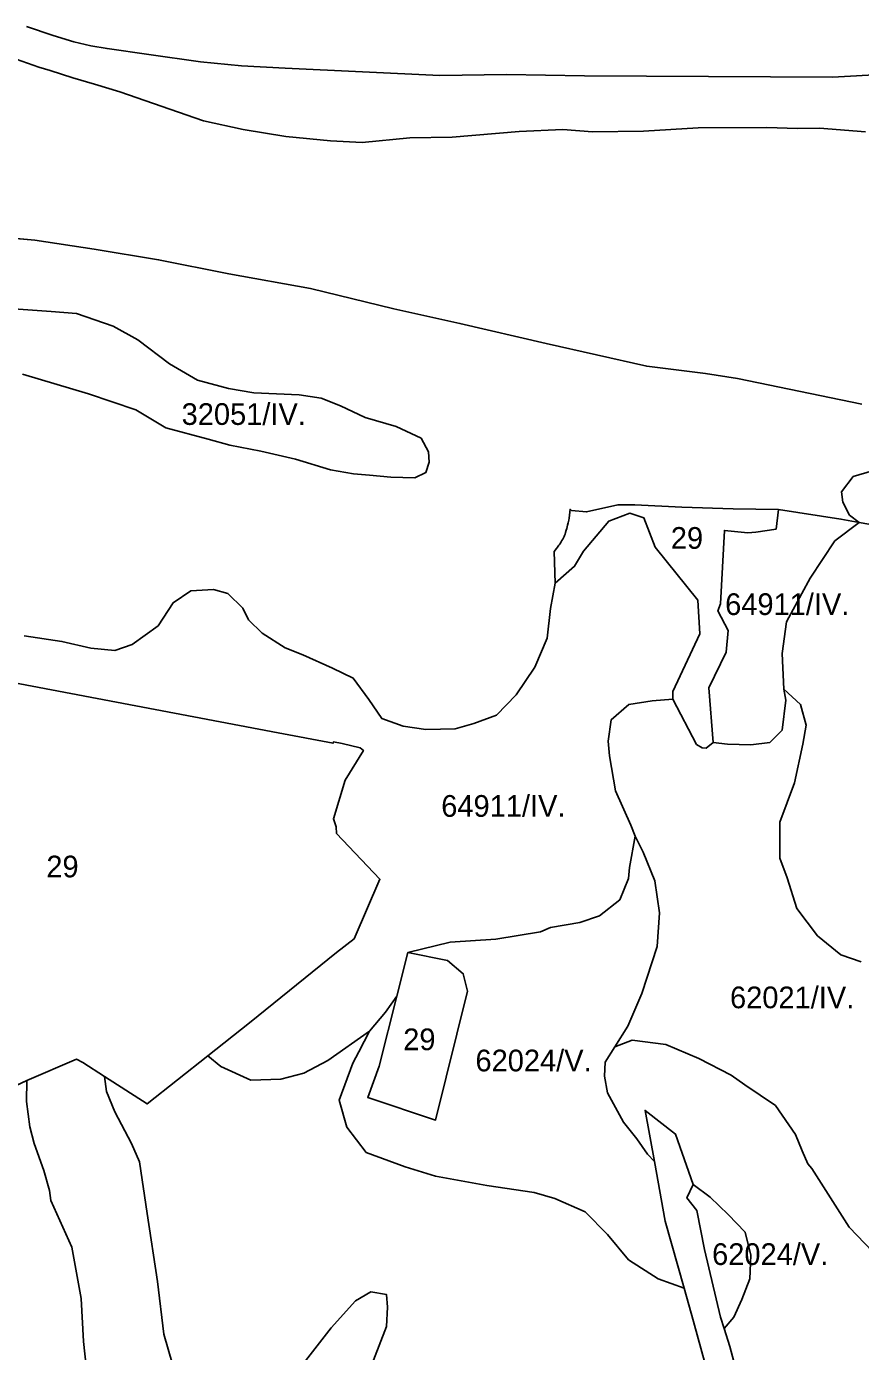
# Model space of a CAD drawing. Extents: x -521621 to -516761, y -1190184 to -1184927.
# Drawn here: x -519686 to -519109, y -1188092 to -1187176 of the extents above; entities that cross this region are included whole.
import ezdxf

# ---------------------------------------------------------------- set-up
doc = ezdxf.new("R2010")
doc.units = 0
doc.layers.add('BPEJ_s', color=7, linetype='Continuous')

msp = doc.modelspace()

# ---------------------------------------------------------------- linework, layer by layer
at = {"layer": 'BPEJ_s'}
for p, q in [((-519667.22, -1187182.03), (-519685.69, -1187175.9)), ((-519652.89, -1187186.47), (-519667.22, -1187182.03)), ((-519641.3, -1187189.2), (-519652.89, -1187186.47)), ((-519629.99, -1187191.18), (-519641.3, -1187189.2)), ((-519601.06, -1187195.24), (-519629.99, -1187191.18)), ((-519565.43, -1187200.37), (-519601.06, -1187195.24)), ((-519536.97, -1187203.2), (-519565.43, -1187200.37)), ((-519506.81, -1187204.71), (-519536.97, -1187203.2)), ((-519400, -1187209.9), (-519506.81, -1187204.71)), ((-519353.85, -1187209.13), (-519400, -1187209.9)), ((-519299.97, -1187210.03), (-519353.85, -1187209.13)), ((-519128.66, -1187211.03), (-519299.97, -1187210.03)), ((-519112.11, -1187210), (-519128.66, -1187211.03)), ((-519092.1, -1187208.96), (-519112.11, -1187210)), ((-519733.29, -1187318.93), (-519679.94, -1187323.59)), ((-519679.94, -1187323.59), (-519638.88, -1187329.95)), ((-519638.88, -1187329.95), (-519594.42, -1187337.15)), ((-519594.42, -1187337.15), (-519545.74, -1187346.89)), ((-519545.74, -1187346.89), (-519489.43, -1187357.06)), ((-519489.43, -1187357.06), (-519431.85, -1187371.04)), ((-519668.66, -1187373.03), (-519694.32, -1187371.13)), ((-519651.08, -1187374.46), (-519668.66, -1187373.03)), ((-519625.89, -1187383.02), (-519651.08, -1187374.46)), ((-519431.85, -1187371.04), (-519386.13, -1187381.21)), ((-519608.78, -1187392.53), (-519625.89, -1187383.02)), ((-519386.13, -1187381.21), (-519326.43, -1187395.19)), ((-519586.93, -1187409.17), (-519608.78, -1187392.53)), ((-519326.43, -1187395.19), (-519257, -1187410.86)), ((-519567.44, -1187420.58), (-519586.93, -1187409.17)), ((-519257, -1187410.86), (-519216.36, -1187415.95)), ((-519688.33, -1187416.31), (-519642.89, -1187429.9)), ((-519546.06, -1187426.29), (-519567.44, -1187420.58)), ((-519216.36, -1187415.95), (-519194.34, -1187419.33)), ((-519194.34, -1187419.33), (-519108.4, -1187437.13)), ((-519642.89, -1187429.9), (-519610.01, -1187441.1)), ((-519528.48, -1187429.14), (-519546.06, -1187426.29)), ((-519497.12, -1187430.57), (-519528.48, -1187429.14)), ((-519481.91, -1187432.94), (-519497.12, -1187430.57)), ((-519468.6, -1187438.17), (-519481.91, -1187432.94)), ((-519610.01, -1187441.1), (-519589.34, -1187453.42)), ((-519451.5, -1187446.26), (-519468.6, -1187438.17)), ((-519430.11, -1187452.44), (-519451.5, -1187446.26)), ((-519589.34, -1187453.42), (-519560.09, -1187461.28)), ((-519560.09, -1187461.28), (-519545.1, -1187465.54)), ((-519413.01, -1187460.52), (-519430.11, -1187452.44)), ((-519407.78, -1187470.03), (-519413.01, -1187460.52)), ((-519545.1, -1187465.54), (-519523.8, -1187469.49)), ((-519523.8, -1187469.49), (-519499.82, -1187475.02)), ((-519407.31, -1187477.16), (-519407.78, -1187470.03)), ((-519499.82, -1187475.02), (-519475.49, -1187482.38)), ((-519409.68, -1187484.3), (-519407.31, -1187477.16)), ((-519475.49, -1187482.38), (-519459.58, -1187485.25)), ((-519459.58, -1187485.25), (-519448.65, -1187486.2)), ((-519448.65, -1187486.2), (-519433.92, -1187487.62)), ((-519433.92, -1187487.62), (-519417.28, -1187488.1)), ((-519417.28, -1187488.1), (-519409.68, -1187484.3)), ((-519114.33, -1187487.11), (-519122.37, -1187497.71)), ((-519091.46, -1187480.34), (-519114.33, -1187487.11)), ((-519122.37, -1187497.71), (-519121.52, -1187504.91)), ((-519277.01, -1187506.71), (-519298.64, -1187511.54)), ((-519265.28, -1187506.76), (-519277.01, -1187506.71)), ((-519232.85, -1187508.38), (-519265.28, -1187506.76)), ((-519121.52, -1187504.91), (-519116.87, -1187513.8)), ((-519310.7, -1187515.97), (-519310.93, -1187517.36)), ((-519310.41, -1187513.76), (-519310.7, -1187515.97)), ((-519310.01, -1187509.72), (-519310.41, -1187513.76)), ((-519308.94, -1187510.56), (-519310.01, -1187509.72)), ((-519298.64, -1187511.54), (-519308.94, -1187510.56)), ((-519197.25, -1187509.54), (-519232.85, -1187508.38)), ((-519165.96, -1187509.87), (-519197.25, -1187509.54)), ((-519122.78, -1187516.59), (-519165.96, -1187509.87)), ((-519116.87, -1187513.8), (-519110.16, -1187518.97)), ((-519312.6, -1187524.31), (-519313.08, -1187525.9)), ((-519312.25, -1187523.11), (-519312.6, -1187524.31)), ((-519311.66, -1187520.8), (-519312.25, -1187523.11)), ((-519311.26, -1187519.05), (-519311.66, -1187520.8)), ((-519310.93, -1187517.36), (-519311.26, -1187519.05)), ((-519110.16, -1187518.97), (-519122.78, -1187516.59)), ((-519317.68, -1187534.57), (-519318.15, -1187535.24)), ((-519317.17, -1187533.79), (-519317.68, -1187534.57)), ((-519316.15, -1187532.17), (-519317.17, -1187533.79)), ((-519315.65, -1187531.35), (-519316.15, -1187532.17)), ((-519315.08, -1187530.38), (-519315.65, -1187531.35)), ((-519314.59, -1187529.47), (-519315.08, -1187530.38)), ((-519314.19, -1187528.68), (-519314.59, -1187529.47)), ((-519313.82, -1187527.87), (-519314.19, -1187528.68)), ((-519313.45, -1187526.94), (-519313.82, -1187527.87)), ((-519313.08, -1187525.9), (-519313.45, -1187526.94)), ((-519319.39, -1187536.9), (-519321.02, -1187538.88)), ((-519321.02, -1187538.88), (-519320.31, -1187560.93)), ((-519318.69, -1187535.99), (-519319.39, -1187536.9)), ((-519318.15, -1187535.24), (-519318.69, -1187535.99)), ((-519320.31, -1187560.93), (-519323.61, -1187578.33)), ((-519572.15, -1187566.12), (-519584.35, -1187574.45)), ((-519556.33, -1187565.29), (-519572.15, -1187566.12)), ((-519546.63, -1187568.06), (-519556.33, -1187565.29)), ((-519536.09, -1187578.06), (-519546.63, -1187568.06)), ((-519584.35, -1187574.45), (-519594.61, -1187590.27)), ((-519532.2, -1187586.11), (-519536.09, -1187578.06)), ((-519323.61, -1187578.33), (-519325.83, -1187598.87)), ((-519522.77, -1187595.54), (-519532.2, -1187586.11)), ((-519661.18, -1187601.09), (-519687.26, -1187597.21)), ((-519594.61, -1187590.27), (-519612.64, -1187603.31)), ((-519506.96, -1187605.53), (-519522.77, -1187595.54)), ((-519641.21, -1187605.81), (-519661.18, -1187601.09)), ((-519624.57, -1187607.48), (-519641.21, -1187605.81)), ((-519612.64, -1187603.31), (-519624.57, -1187607.48)), ((-519494.76, -1187610.53), (-519506.96, -1187605.53)), ((-519325.83, -1187598.87), (-519334.43, -1187618.86)), ((-519474.23, -1187619.69), (-519494.76, -1187610.53)), ((-519459.81, -1187626.63), (-519474.23, -1187619.69)), ((-519334.43, -1187618.86), (-519347.19, -1187638.01)), ((-519448.99, -1187641.34), (-519459.81, -1187626.63)), ((-519440.11, -1187654.38), (-519448.99, -1187641.34)), ((-519347.19, -1187638.01), (-519360.78, -1187652.16)), ((-519360.78, -1187652.16), (-519376.59, -1187657.99)), ((-519425.41, -1187659.66), (-519440.11, -1187654.38)), ((-519409.6, -1187662.15), (-519425.41, -1187659.66)), ((-519389.35, -1187661.6), (-519409.6, -1187662.15)), ((-519376.59, -1187657.99), (-519389.35, -1187661.6)), ((-519710.91, -1187916.7), (-519685.53, -1187904.73)), ((-519685.53, -1187904.73), (-519685.65, -1187919.2)), ((-519685.65, -1187919.2), (-519683.42, -1187936.76)), ((-519683.42, -1187936.76), (-519680.31, -1187948.33)), ((-519680.31, -1187948.33), (-519673.65, -1187967)), ((-519673.65, -1187967), (-519669.87, -1187980.79)), ((-519669.87, -1187980.79), (-519668.9, -1187987.88)), ((-519668.9, -1187987.88), (-519654.42, -1188020.09)), ((-519654.42, -1188020.09), (-519647.98, -1188055.52)), ((-519647.98, -1188055.52), (-519646.37, -1188085.32)), ((-519646.37, -1188085.32), (-519639.13, -1188151.35))]:
    msp.add_line(p, q, dxfattribs=at)
for points in [[(-519685.69, -1187175.9), (-519667.22, -1187182.03), (-519652.89, -1187186.47), (-519641.3, -1187189.2), (-519629.99, -1187191.18), (-519601.06, -1187195.24), (-519565.43, -1187200.37), (-519536.97, -1187203.2), (-519506.81, -1187204.71), (-519400, -1187209.9), (-519353.85, -1187209.13), (-519299.97, -1187210.03), (-519128.66, -1187211.03), (-519112.11, -1187210), (-519092.1, -1187208.96), (-519064.5, -1187207.92), (-519024.83, -1187208.61), (-519003.79, -1187209.3), (-518919.06, -1187210.79), (-518913.41, -1187211.72)], [(-519696.84, -1187197.02), (-519677.05, -1187204.06), (-519669.31, -1187206.37), (-519653.61, -1187211.29), (-519638.75, -1187215.67), (-519621.13, -1187221.16), (-519563.24, -1187241.16), (-519535.84, -1187247.13), (-519506.38, -1187252.08), (-519475.48, -1187254.97), (-519453.65, -1187256.21), (-519420.68, -1187252.91), (-519391.43, -1187252.49), (-519345.28, -1187248.58), (-519315, -1187247.13), (-519294.6, -1187248.78), (-519259.17, -1187248.17), (-519221.47, -1187245.9), (-519174.09, -1187245.69), (-519152.82, -1187246.42), (-519137.62, -1187246.1), (-519105.9, -1187248.79)], [(-519105.9, -1187248.79), (-519137.62, -1187246.1), (-519152.82, -1187246.42), (-519174.09, -1187245.69), (-519221.47, -1187245.9), (-519259.17, -1187248.17), (-519294.6, -1187248.78), (-519315, -1187247.13), (-519345.28, -1187248.58), (-519391.43, -1187252.49), (-519420.68, -1187252.91), (-519453.65, -1187256.21), (-519475.48, -1187254.97), (-519506.38, -1187252.08), (-519535.84, -1187247.13), (-519563.24, -1187241.16), (-519621.13, -1187221.16), (-519638.75, -1187215.67), (-519653.61, -1187211.29), (-519669.31, -1187206.37), (-519677.05, -1187204.06), (-519696.84, -1187197.02)], [(-519108.4, -1187437.13), (-519194.34, -1187419.33), (-519216.36, -1187415.95), (-519257, -1187410.86), (-519326.43, -1187395.19), (-519386.13, -1187381.21), (-519431.85, -1187371.04), (-519489.43, -1187357.06), (-519545.74, -1187346.89), (-519594.42, -1187337.15), (-519638.88, -1187329.95), (-519679.94, -1187323.59), (-519733.29, -1187318.93)], [(-519694.32, -1187371.13), (-519668.66, -1187373.03), (-519651.08, -1187374.46), (-519625.89, -1187383.02), (-519608.78, -1187392.53), (-519586.93, -1187409.17), (-519567.44, -1187420.58), (-519546.06, -1187426.29), (-519528.48, -1187429.14), (-519497.12, -1187430.57), (-519481.91, -1187432.94), (-519468.6, -1187438.17), (-519451.5, -1187446.26), (-519430.11, -1187452.44), (-519413.01, -1187460.52), (-519407.78, -1187470.03), (-519407.31, -1187477.16), (-519409.68, -1187484.3), (-519417.28, -1187488.1), (-519433.92, -1187487.62), (-519448.65, -1187486.2), (-519459.58, -1187485.25), (-519475.49, -1187482.38), (-519499.82, -1187475.02), (-519523.8, -1187469.49), (-519545.1, -1187465.54), (-519560.09, -1187461.28), (-519589.34, -1187453.42), (-519610.01, -1187441.1), (-519642.89, -1187429.9), (-519688.33, -1187416.31)], [(-519055.51, -1187528.45), (-519110.16, -1187518.97), (-519116.87, -1187513.8), (-519121.52, -1187504.91), (-519122.37, -1187497.71), (-519114.33, -1187487.11), (-519091.46, -1187480.34)], [(-519687.26, -1187597.21), (-519661.18, -1187601.09), (-519641.21, -1187605.81), (-519624.57, -1187607.48), (-519612.64, -1187603.31), (-519594.61, -1187590.27), (-519584.35, -1187574.45), (-519572.15, -1187566.12), (-519556.33, -1187565.29), (-519546.63, -1187568.06), (-519536.09, -1187578.06), (-519532.2, -1187586.11), (-519522.77, -1187595.54), (-519506.96, -1187605.53), (-519494.76, -1187610.53), (-519474.23, -1187619.69), (-519459.81, -1187626.63), (-519448.99, -1187641.34), (-519440.11, -1187654.38), (-519425.41, -1187659.66), (-519409.6, -1187662.15), (-519389.35, -1187661.6), (-519376.59, -1187657.99), (-519360.78, -1187652.16), (-519347.19, -1187638.01), (-519334.43, -1187618.86), (-519325.83, -1187598.87), (-519323.61, -1187578.33), (-519320.31, -1187560.93), (-519306.91, -1187549.18), (-519300.78, -1187538.69), (-519283.32, -1187517.95), (-519268.8, -1187512.49), (-519258.98, -1187515.74), (-519251.29, -1187535.93), (-519221.71, -1187572.62), (-519220.42, -1187595.79), (-519239.07, -1187635.7), (-519239.07, -1187641.18), (-519253.19, -1187642.16), (-519269.28, -1187644.7), (-519281.56, -1187655.29), (-519283.67, -1187670.12), (-519282.83, -1187680.29), (-519278.59, -1187704.44), (-519268.01, -1187728.16), (-519265.04, -1187735.78), (-519268.85, -1187757.39), (-519269.7, -1187765.01), (-519275.63, -1187779.84), (-519289.6, -1187790.85), (-519303.15, -1187795.52), (-519323.47, -1187798.9), (-519330.33, -1187802.04), (-519361.24, -1187806.96), (-519392.85, -1187809.07), (-519422.03, -1187816.17), (-519429.72, -1187846.45), (-519437.46, -1187857.57), (-519448.7, -1187870.58), (-519477.51, -1187890.97), (-519494.02, -1187899.75), (-519509.82, -1187903.97), (-519530.55, -1187904.67), (-519551.27, -1187895.18), (-519560.37, -1187887.81), (-519531.55, -1187865), (-519471.37, -1187816.27), (-519459.2, -1187806.79), (-519441.4, -1187765.6), (-519471.42, -1187734.06), (-519471.72, -1187729.26), (-519473.52, -1187723.85), (-519465.47, -1187697.1), (-519452.88, -1187676.55), (-519455.1, -1187674.65), (-519467.57, -1187671.74), (-519473.61, -1187670.59), (-519473.79, -1187671.56), (-519511.79, -1187664.33), (-519695.16, -1187629.58)], [(-519108.82, -1187822.63), (-519122.79, -1187817.97), (-519138.88, -1187804.83), (-519153.28, -1187785.77), (-519160.05, -1187764.59), (-519165.13, -1187751.03), (-519165.13, -1187726.04), (-519154.97, -1187698.93), (-519149.04, -1187672.24), (-519146.93, -1187659.11), (-519150.74, -1187644.7), (-519162.17, -1187634.11), (-519163.44, -1187609.54), (-519160.47, -1187587.51), (-519149.89, -1187568.03), (-519143.96, -1187557.44), (-519127.03, -1187531.59), (-519110.16, -1187518.97), (-519055.51, -1187528.45)], [(-519695.16, -1187629.58), (-519511.79, -1187664.33), (-519473.79, -1187671.56), (-519473.61, -1187670.59), (-519467.57, -1187671.74), (-519455.1, -1187674.65), (-519452.88, -1187676.55), (-519465.47, -1187697.1), (-519473.52, -1187723.85), (-519471.72, -1187729.26), (-519471.42, -1187734.06), (-519441.4, -1187765.6), (-519459.2, -1187806.79), (-519471.37, -1187816.27), (-519531.55, -1187865), (-519560.37, -1187887.81), (-519602.33, -1187921.01), (-519631.66, -1187902.09), (-519646.68, -1187892.41), (-519651.15, -1187890.15), (-519685.53, -1187904.73), (-519710.91, -1187916.7)], [(-519095.38, -1188028.82), (-519117.18, -1188006.2), (-519142.95, -1187965.74), (-519145.66, -1187962.42), (-519149.47, -1187953.53), (-519154.12, -1187942.09), (-519168.09, -1187922.18), (-519189.26, -1187907.78), (-519198.58, -1187901), (-519221.01, -1187889.56), (-519243.88, -1187879.82), (-519267.16, -1187876.85), (-519279.02, -1187881.51), (-519270.12, -1187867.11), (-519260.39, -1187844.66), (-519249.8, -1187812.04), (-519248.11, -1187788.74), (-519251.5, -1187766.71), (-519259.54, -1187746.8), (-519265.04, -1187735.78), (-519268.01, -1187728.16), (-519278.59, -1187704.44), (-519282.83, -1187680.29), (-519283.67, -1187670.12), (-519281.56, -1187655.29), (-519269.28, -1187644.7), (-519253.19, -1187642.16), (-519239.07, -1187641.18), (-519222.67, -1187672.4), (-519218.81, -1187674.65), (-519215.92, -1187674.97), (-519211.1, -1187671.11), (-519201.12, -1187672.24), (-519185.03, -1187672.66), (-519171.9, -1187670.97), (-519163.44, -1187662.5), (-519160.9, -1187641.74), (-519162.17, -1187634.11), (-519150.74, -1187644.7), (-519146.93, -1187659.11), (-519149.04, -1187672.24), (-519154.97, -1187698.93), (-519165.13, -1187726.04), (-519165.13, -1187751.03), (-519160.05, -1187764.59), (-519153.28, -1187785.77), (-519138.88, -1187804.83), (-519122.79, -1187817.97), (-519108.82, -1187822.63)], [(-519581.87, -1188111.43), (-519590.76, -1188080.3), (-519595.2, -1188043.83), (-519602.31, -1187996.69), (-519607.65, -1187961.11), (-519613.1, -1187948.26), (-519624.69, -1187926.47), (-519630.31, -1187912.41), (-519631.66, -1187902.09), (-519602.33, -1187921.01), (-519560.37, -1187887.81), (-519551.27, -1187895.18), (-519530.55, -1187904.67), (-519509.82, -1187903.97), (-519494.02, -1187899.75), (-519477.51, -1187890.97), (-519448.7, -1187870.58), (-519456.08, -1187884.99), (-519460.21, -1187892.8), (-519469.54, -1187918.48), (-519464.29, -1187937.15), (-519450.88, -1187954.65), (-519424.06, -1187964.57), (-519403.06, -1187970.99), (-519367.49, -1187977.41), (-519334.84, -1187982.22), (-519320.55, -1187986.31), (-519299.56, -1187995.64), (-519284.11, -1188011.39), (-519269.53, -1188028.9), (-519249.12, -1188042.03), (-519231.21, -1188048.3), (-519224.72, -1188071.37), (-519213.76, -1188110.85)], [(-519184.34, -1188145.83), (-519199.49, -1188088.69), (-519203.45, -1188076.36), (-519196.87, -1188068.49), (-519191.32, -1188056.19), (-519185.77, -1188041.91), (-519184.98, -1188025.64), (-519188.94, -1188009.77), (-519200.84, -1187997.48), (-519213.13, -1187985.57), (-519225, -1187976.8), (-519237.22, -1187941.87), (-519258.16, -1187925.51), (-519251.75, -1187960.69), (-519256.58, -1187955.65), (-519263.77, -1187945.06), (-519273.09, -1187933.62), (-519284.1, -1187913.28), (-519286.21, -1187901.84), (-519285.79, -1187892.1), (-519279.02, -1187881.51), (-519267.16, -1187876.85), (-519243.88, -1187879.82), (-519221.01, -1187889.56), (-519198.58, -1187901), (-519189.26, -1187907.78), (-519168.09, -1187922.18), (-519154.12, -1187942.09), (-519149.47, -1187953.53), (-519145.66, -1187962.42), (-519142.95, -1187965.74), (-519117.18, -1188006.2), (-519095.38, -1188028.82)], [(-519639.13, -1188151.35), (-519646.37, -1188085.32), (-519647.98, -1188055.52), (-519654.42, -1188020.09), (-519668.9, -1187987.88), (-519669.87, -1187980.79), (-519673.65, -1187967), (-519680.31, -1187948.33), (-519683.42, -1187936.76), (-519685.65, -1187919.2), (-519685.53, -1187904.73), (-519651.15, -1187890.15), (-519646.68, -1187892.41), (-519631.66, -1187902.09), (-519630.31, -1187912.41), (-519624.69, -1187926.47), (-519613.1, -1187948.26), (-519607.65, -1187961.11), (-519602.31, -1187996.69), (-519595.2, -1188043.83), (-519590.76, -1188080.3), (-519581.87, -1188111.43)], [(-519213.76, -1188110.85), (-519224.72, -1188071.37), (-519231.21, -1188048.3), (-519244.2, -1188002.13), (-519251.75, -1187960.69), (-519258.16, -1187925.51), (-519237.22, -1187941.87), (-519225, -1187976.8), (-519229.37, -1187985.97), (-519222.39, -1187994.71), (-519217, -1188021.74), (-519205.97, -1188068.51), (-519203.45, -1188076.36), (-519199.49, -1188088.69), (-519184.34, -1188145.83)], [(-519445.87, -1188098.08), (-519436.98, -1188074.96), (-519436.09, -1188061.62), (-519436.98, -1188052.72), (-519447.65, -1188050.95), (-519458.31, -1188057.17), (-519475.2, -1188075.85), (-519499.2, -1188106.98)], [(-519499.2, -1188106.98), (-519475.2, -1188075.85), (-519458.31, -1188057.17), (-519447.65, -1188050.95), (-519436.98, -1188052.72), (-519436.09, -1188061.62), (-519436.98, -1188074.96), (-519445.87, -1188098.08)]]:
    msp.add_lwpolyline(points, dxfattribs=at)
for points in [[(-519320.31, -1187560.93), (-519321.02, -1187538.88), (-519319.39, -1187536.9), (-519318.69, -1187535.99), (-519318.15, -1187535.24), (-519317.68, -1187534.57), (-519317.17, -1187533.79), (-519316.15, -1187532.17), (-519315.65, -1187531.35), (-519315.08, -1187530.38), (-519314.59, -1187529.47), (-519314.19, -1187528.68), (-519313.82, -1187527.87), (-519313.45, -1187526.94), (-519313.08, -1187525.9), (-519312.6, -1187524.31), (-519312.25, -1187523.11), (-519311.66, -1187520.8), (-519311.26, -1187519.05), (-519310.93, -1187517.36), (-519310.7, -1187515.97), (-519310.41, -1187513.76), (-519310.01, -1187509.72), (-519308.94, -1187510.56), (-519298.64, -1187511.54), (-519277.01, -1187506.71), (-519265.28, -1187506.76), (-519232.85, -1187508.38), (-519197.25, -1187509.54), (-519165.96, -1187509.87), (-519167.64, -1187523.44), (-519181.66, -1187525.7), (-519187.08, -1187526.15), (-519203.36, -1187524.34), (-519205.95, -1187575.2), (-519207.88, -1187580.02), (-519200.81, -1187593.54), (-519202.09, -1187608.67), (-519213.99, -1187633.13), (-519211.1, -1187671.11), (-519215.92, -1187674.97), (-519218.81, -1187674.65), (-519222.67, -1187672.4), (-519239.07, -1187641.18), (-519239.07, -1187635.7), (-519220.42, -1187595.79), (-519221.71, -1187572.62), (-519251.29, -1187535.93), (-519258.98, -1187515.74), (-519268.8, -1187512.49), (-519283.32, -1187517.95), (-519300.78, -1187538.69), (-519306.91, -1187549.18)], [(-519211.1, -1187671.11), (-519213.99, -1187633.13), (-519202.09, -1187608.67), (-519200.81, -1187593.54), (-519207.88, -1187580.02), (-519205.95, -1187575.2), (-519203.36, -1187524.34), (-519187.08, -1187526.15), (-519181.66, -1187525.7), (-519167.64, -1187523.44), (-519165.96, -1187509.87), (-519122.78, -1187516.59), (-519110.16, -1187518.97), (-519127.03, -1187531.59), (-519143.96, -1187557.44), (-519149.89, -1187568.03), (-519160.47, -1187587.51), (-519163.44, -1187609.54), (-519162.17, -1187634.11), (-519160.9, -1187641.74), (-519163.44, -1187662.5), (-519171.9, -1187670.97), (-519185.03, -1187672.66), (-519201.12, -1187672.24)], [(-519448.7, -1187870.58), (-519437.46, -1187857.57), (-519429.72, -1187846.45), (-519441.99, -1187894.78), (-519449.8, -1187916.5), (-519402.93, -1187932.13), (-519380.8, -1187843.1), (-519383.84, -1187830.94), (-519394.69, -1187821.82), (-519422.03, -1187816.17), (-519392.85, -1187809.07), (-519361.24, -1187806.96), (-519330.33, -1187802.04), (-519323.47, -1187798.9), (-519303.15, -1187795.52), (-519289.6, -1187790.85), (-519275.63, -1187779.84), (-519269.7, -1187765.01), (-519268.85, -1187757.39), (-519265.04, -1187735.78), (-519259.54, -1187746.8), (-519251.5, -1187766.71), (-519248.11, -1187788.74), (-519249.8, -1187812.04), (-519260.39, -1187844.66), (-519270.12, -1187867.11), (-519279.02, -1187881.51), (-519285.79, -1187892.1), (-519286.21, -1187901.84), (-519284.1, -1187913.28), (-519273.09, -1187933.62), (-519263.77, -1187945.06), (-519256.58, -1187955.65), (-519251.75, -1187960.69), (-519244.2, -1188002.13), (-519231.21, -1188048.3), (-519249.12, -1188042.03), (-519269.53, -1188028.9), (-519284.11, -1188011.39), (-519299.56, -1187995.64), (-519320.55, -1187986.31), (-519334.84, -1187982.22), (-519367.49, -1187977.41), (-519403.06, -1187970.99), (-519424.06, -1187964.57), (-519450.88, -1187954.65), (-519464.29, -1187937.15), (-519469.54, -1187918.48), (-519460.21, -1187892.8), (-519456.08, -1187884.99)], [(-519429.72, -1187846.45), (-519422.03, -1187816.17), (-519394.69, -1187821.82), (-519383.84, -1187830.94), (-519380.8, -1187843.1), (-519402.93, -1187932.13), (-519449.8, -1187916.5), (-519441.99, -1187894.78)], [(-519225, -1187976.8), (-519213.13, -1187985.57), (-519200.84, -1187997.48), (-519188.94, -1188009.77), (-519184.98, -1188025.64), (-519185.77, -1188041.91), (-519191.32, -1188056.19), (-519196.87, -1188068.49), (-519203.45, -1188076.36), (-519205.97, -1188068.51), (-519217, -1188021.74), (-519222.39, -1187994.71), (-519229.37, -1187985.97)]]:
    msp.add_lwpolyline(points, close=True, dxfattribs=at)

# ---------------------------------------------------------------- texts
for s, p in [('32051/IV.', (-519578.45, -1187451.42)), ('29', (-519240.36, -1187537.09)), ('64911/IV.', (-519202.82, -1187582.89)), ('64911/IV.', (-519399.03, -1187722.42)), ('29', (-519671.97, -1187764.3)), ('62021/IV.', (-519199.44, -1187854.82)), ('29', (-519425.31, -1187883.82)), ('62024/V.', (-519375.39, -1187898.46)), ('62024/V.', (-519211.83, -1188032.36))]:
    msp.add_text(s, height=15, dxfattribs=at).set_placement(p)

doc.saveas('drawing.dxf')
